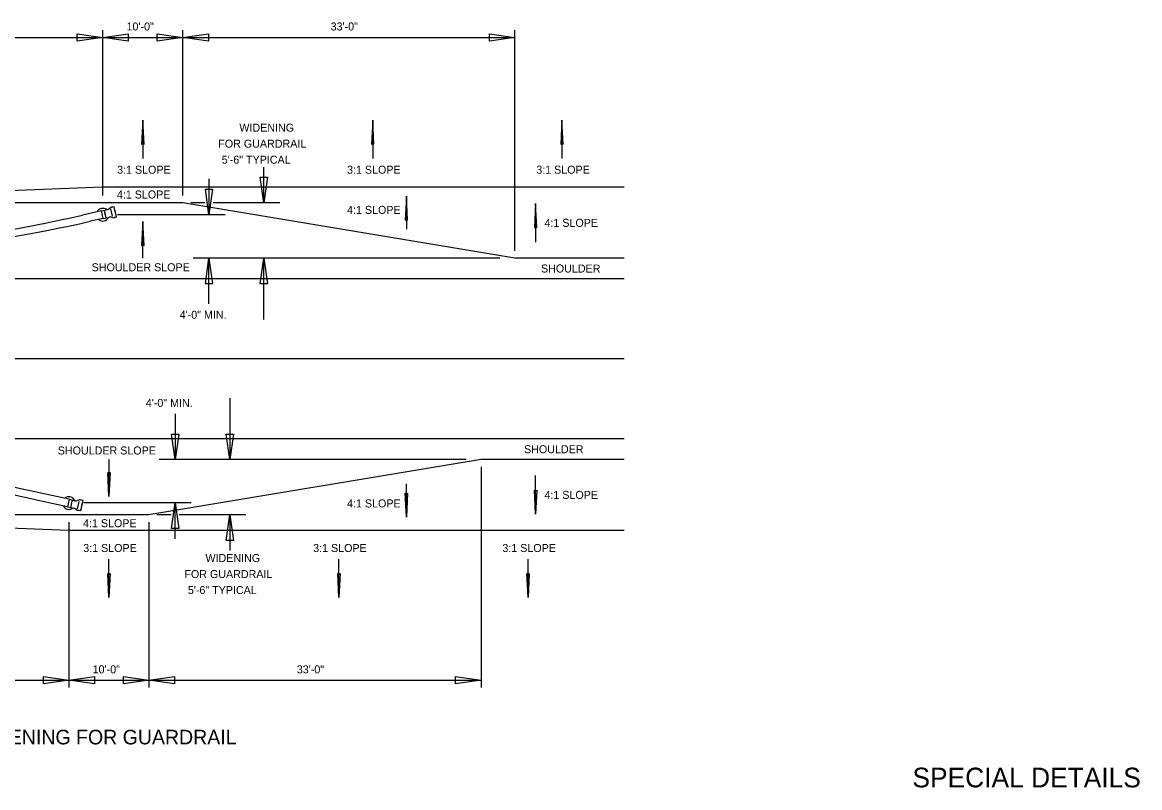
# Model space of a CAD drawing. Extents: x -149 to 1228740, y -106 to 152440.
# Drawn here: x -81.8 to -5.2, y -106 to -53.6 of the extents above; entities that cross this region are included whole.
import ezdxf

# ---------------------------------------------------------------- set-up
doc = ezdxf.new("R2010")
doc.units = 0
for name, color, linetype in [('R_Annotation', 7, 'Continuous'), ('R_Centerline', 7, 'Continuous'), ('R_Dimension', 7, 'Continuous'), ('R_Proposed Road', 7, 'Continuous'), ('R_Proposed Road_Lane', 7, 'Continuous'), ('R_Proposed Road_Shoulder', 7, 'Continuous'), ('R_Striping', 7, 'Continuous'), ('R_Water', 7, 'Continuous')]:
    doc.layers.add(name, color=color, linetype=linetype)

msp = doc.modelspace()

# ---------------------------------------------------------------- linework, layer by layer
at = {"layer": 'R_Annotation'}
for p, q in [((-73.52, -60.296), (-73.52, -62.938)), ((-57.763, -60.296), (-57.763, -62.938)), ((-44.799, -60.296), (-44.799, -62.938)), ((-55.458, -65.503), (-55.458, -67.782)), ((-46.61, -66.015), (-46.61, -68.657)), ((-73.52, -69.758), (-73.52, -67.236)), ((-75.84, -83.56), (-75.84, -86.082)), ((-46.61, -87.303), (-46.61, -84.661)), ((-55.458, -87.514), (-55.458, -85.235)), ((-75.84, -93.022), (-75.84, -90.38)), ((-60.084, -93.022), (-60.084, -90.38)), ((-47.12, -93.022), (-47.12, -90.38))]:
    msp.add_line(p, q, dxfattribs=at)
for points in [[(-73.52, -60.296), (-73.602, -61.941), (-73.52, -61.896), (-73.437, -61.941)], [(-57.763, -60.296), (-57.846, -61.941), (-57.763, -61.896), (-57.681, -61.941)], [(-44.799, -60.296), (-44.882, -61.941), (-44.799, -61.896), (-44.717, -61.941)], [(-55.458, -65.503), (-55.54, -67.148), (-55.458, -67.102), (-55.375, -67.148)], [(-46.61, -66.015), (-46.692, -67.661), (-46.61, -67.615), (-46.527, -67.661)], [(-73.52, -67.236), (-73.602, -68.882), (-73.52, -68.836), (-73.437, -68.882)], [(-75.84, -86.082), (-75.923, -84.437), (-75.84, -84.482), (-75.758, -84.437)], [(-46.61, -87.303), (-46.692, -85.658), (-46.61, -85.703), (-46.527, -85.658)], [(-55.458, -87.514), (-55.54, -85.869), (-55.458, -85.915), (-55.375, -85.869)], [(-75.84, -93.022), (-75.923, -91.377), (-75.84, -91.422), (-75.758, -91.377)], [(-60.084, -93.022), (-60.166, -91.377), (-60.084, -91.422), (-60.002, -91.377)], [(-47.12, -93.022), (-47.202, -91.377), (-47.12, -91.422), (-47.038, -91.377)]]:
    msp.add_lwpolyline(points, close=True, dxfattribs=at)
at = {"layer": 'R_Centerline'}
msp.add_line((-40.54, -76.659), (-122.83, -76.659), dxfattribs=at)
at = {"layer": 'R_Dimension'}
for p, q in [((-76.262, -65.465), (-76.262, -54.129)), ((-70.778, -65.465), (-70.778, -54.129)), ((-48.02, -69.258), (-48.02, -54.129)), ((-103.681, -54.629), (-76.262, -54.629)), ((-76.262, -54.629), (-70.778, -54.629)), ((-70.778, -54.629), (-48.02, -54.629)), ((-65.236, -65.965), (-65.236, -63.528)), ((-68.985, -64.322), (-68.985, -66.788)), ((-69.259, -65.965), (-70.229, -65.965)), ((-64.139, -65.965), (-68.71, -65.965)), ((-67.888, -66.788), (-75.249, -66.788)), ((-65.236, -73.96), (-65.236, -69.758)), ((-67.557, -79.358), (-67.557, -83.56)), ((-50.339, -84.06), (-50.339, -99.189)), ((-70.209, -86.53), (-77.57, -86.53)), ((-71.305, -88.997), (-71.305, -86.53)), ((-78.582, -87.853), (-78.582, -99.189)), ((-73.098, -87.853), (-73.098, -99.189)), ((-71.58, -87.353), (-72.55, -87.353)), ((-66.46, -87.353), (-71.031, -87.353)), ((-67.557, -87.353), (-67.557, -89.79)), ((-106.002, -98.689), (-78.582, -98.689)), ((-78.582, -98.689), (-73.098, -98.689)), ((-73.098, -98.689), (-50.339, -98.689))]:
    msp.add_line(p, q, dxfattribs=at)
for points in [[(-78.012, -54.379), (-76.262, -54.629), (-78.012, -54.879)], [(-74.512, -54.879), (-76.262, -54.629), (-74.512, -54.379)], [(-72.528, -54.379), (-70.778, -54.629), (-72.528, -54.879)], [(-69.028, -54.879), (-70.778, -54.629), (-69.028, -54.379)], [(-49.77, -54.379), (-48.02, -54.629), (-49.77, -54.879)], [(-64.986, -64.215), (-65.236, -65.965), (-65.486, -64.215)], [(-68.735, -65.038), (-68.985, -66.788), (-69.235, -65.038)], [(-69.235, -71.508), (-68.985, -69.758), (-68.735, -71.508)], [(-65.486, -71.508), (-65.236, -69.758), (-64.986, -71.508)], [(-71.055, -81.81), (-71.305, -83.56), (-71.555, -81.81)], [(-67.307, -81.81), (-67.557, -83.56), (-67.807, -81.81)], [(-71.555, -88.28), (-71.305, -86.53), (-71.055, -88.28)], [(-67.807, -89.103), (-67.557, -87.353), (-67.307, -89.103)], [(-80.332, -98.439), (-78.582, -98.689), (-80.332, -98.939)], [(-76.832, -98.939), (-78.582, -98.689), (-76.832, -98.439)], [(-74.848, -98.439), (-73.098, -98.689), (-74.848, -98.939)], [(-71.348, -98.939), (-73.098, -98.689), (-71.348, -98.439)], [(-52.089, -98.439), (-50.339, -98.689), (-52.089, -98.939)]]:
    msp.add_lwpolyline(points, close=True, dxfattribs=at)
for points in [[(-49.054, -69.758), (-70.081, -69.758)], [(-68.985, -72.881), (-68.985, -69.758)], [(-71.305, -80.437), (-71.305, -83.56)], [(-51.373, -83.56), (-61.923, -83.56), (-65.038, -83.56), (-72.402, -83.56)]]:
    msp.add_lwpolyline(points, dxfattribs=at)
at = {"layer": 'R_Proposed Road'}
for p, q in [((-76.359, -66.514), (-77.642, -66.803)), ((-76.359, -66.514), (-75.923, -66.416)), ((-76.242, -67.035), (-76.359, -66.514)), ((-76.035, -66.988), (-76.152, -66.468)), ((-76.122, -66.601), (-76.15, -66.475)), ((-75.744, -66.317), (-75.845, -66.39)), ((-75.589, -66.888), (-75.704, -66.375)), ((-75.479, -66.234), (-75.675, -66.278)), ((-75.608, -66.263), (-75.643, -66.271)), ((-75.459, -66.325), (-75.479, -66.234)), ((-75.318, -66.95), (-75.479, -66.234)), ((-75.428, -66.46), (-75.45, -66.361)), ((-75.401, -66.58), (-75.419, -66.501)), ((-76.242, -67.035), (-77.119, -67.232)), ((-76.242, -67.035), (-75.806, -66.937)), ((-76.075, -66.811), (-76.113, -66.642)), ((-75.592, -66.98), (-75.692, -66.947)), ((-75.418, -66.973), (-75.482, -66.987)), ((-75.318, -66.95), (-75.457, -66.981)), ((-75.372, -66.71), (-75.39, -66.628)), ((-75.342, -66.844), (-75.361, -66.758)), ((-78.563, -86.283), (-79.439, -86.086)), ((-78.563, -86.283), (-78.68, -86.804)), ((-78.563, -86.283), (-78.127, -86.381)), ((-78.356, -86.33), (-78.473, -86.851)), ((-78.395, -86.507), (-78.433, -86.676)), ((-77.909, -86.43), (-78.025, -86.944)), ((-77.913, -86.338), (-78.012, -86.372)), ((-77.739, -86.346), (-77.802, -86.331)), ((-77.639, -86.368), (-77.8, -87.084)), ((-77.639, -86.368), (-77.778, -86.337)), ((-77.663, -86.475), (-77.682, -86.56)), ((-78.68, -86.804), (-79.962, -86.515)), ((-78.68, -86.804), (-78.244, -86.902)), ((-78.443, -86.717), (-78.471, -86.843)), ((-78.065, -87.001), (-78.166, -86.928)), ((-78.065, -87.001), (-78.166, -86.928)), ((-77.8, -87.084), (-77.995, -87.04)), ((-77.8, -87.084), (-77.995, -87.04)), ((-77.929, -87.055), (-77.963, -87.047)), ((-77.929, -87.055), (-77.963, -87.047)), ((-77.779, -86.993), (-77.8, -87.084)), ((-77.779, -86.993), (-77.8, -87.084)), ((-77.749, -86.858), (-77.771, -86.957)), ((-77.722, -86.739), (-77.74, -86.817)), ((-77.693, -86.608), (-77.711, -86.69))]:
    msp.add_line(p, q, dxfattribs=at)
for points in [[(-40.54, -64.89), (-76.262, -64.89), (-103.681, -65.965)], [(-40.54, -88.428), (-78.582, -88.428), (-106.002, -87.353)]]:
    msp.add_lwpolyline(points, dxfattribs=at)
for centre, radius, start, end in [((-76.262, -66.778), 0.435, 52.30361, 152.92389), ((-75.956, -66.191), 0.227, 278.33469, 299.17257), ((-75.956, -66.191), 0.227, 278.33469, 299.17257), ((-75.617, -66.462), 0.193, 107.55156, 131.26204), ((-75.617, -66.462), 0.193, 97.80442, 101.4922), ((-104.241, 51.438), 121.196, 270, 282.67799), ((-101.19, 39.773), 109.68, 270, 282.67799), ((-76.262, -66.778), 0.435, 228.5928, 336.76317), ((-75.76, -67.062), 0.134, 59.28209, 109.60131), ((-75.522, -66.749), 0.241, 253.05396, 285.70011), ((-75.522, -66.749), 0.241, 279.46684, 279.65599), ((-103.511, -193.091), 109.68, 77.32201, 90), ((-106.562, -204.756), 121.196, 77.32201, 90), ((-78.583, -86.54), 0.435, 23.23683, 131.4072), ((-78.081, -86.256), 0.134, 250.39869, 300.71791), ((-77.843, -86.569), 0.241, 74.29989, 106.94604), ((-77.843, -86.569), 0.241, 80.34401, 80.53316), ((-78.583, -86.54), 0.435, 207.07611, 307.69639), ((-78.277, -87.127), 0.227, 60.82743, 81.66531), ((-78.277, -87.127), 0.227, 60.82743, 81.66531), ((-77.937, -86.856), 0.193, 228.73796, 252.44844), ((-77.937, -86.856), 0.193, 228.73796, 252.44844), ((-77.937, -86.856), 0.193, 258.5078, 262.19558), ((-77.937, -86.856), 0.193, 258.5078, 262.19558)]:
    msp.add_arc(centre, radius, start, end, dxfattribs=at)
at = {"layer": 'R_Proposed Road_Lane'}
for points in [[(-40.54, -71.175), (-50.279, -71.175), (-51.306, -71.175), (-59.602, -71.175), (-62.717, -71.175), (-90.137, -71.175), (-96.257, -71.175), (-96.893, -71.175), (-119.858, -71.175)], [(-40.54, -82.143), (-46.457, -82.143), (-47.484, -82.143), (-55.78, -82.143), (-58.895, -82.143), (-86.314, -82.143), (-92.435, -82.143), (-93.071, -82.143), (-122.739, -82.143)]]:
    msp.add_lwpolyline(points, dxfattribs=at)
at = {"layer": 'R_Proposed Road_Shoulder'}
for points in [[(-48.02, -69.758), (-70.778, -65.965), (-113.633, -65.965), (-113.633, -69.21)], [(-40.54, -69.758), (-48.02, -69.758)], [(-50.339, -83.56), (-73.098, -87.353), (-115.953, -87.353), (-115.953, -84.108)], [(-40.54, -83.56), (-50.339, -83.56)]]:
    msp.add_lwpolyline(points, dxfattribs=at)
at = {"layer": 'R_Water'}
for p, q in [((-71.58, -87.353), (-72.55, -87.353)), ((-66.46, -87.353), (-71.031, -87.353))]:
    msp.add_line(p, q, dxfattribs=at)

# ---------------------------------------------------------------- texts
at = {"layer": 'R_Annotation'}
for s, height, p in [('10\'-0"', 0.55, (-74.639, -54.154)), ('33\'-0"', 0.55, (-60.653, -54.154)), ('WIDENING', 0.5484, (-66.905, -61.089)), ('FOR GUARDRAIL', 0.5484, (-68.349, -62.186)), ('5\'-6" TYPICAL', 0.5484, (-68.112, -63.282)), ('3:1 SLOPE', 0.5484, (-75.281, -63.97)), ('3:1 SLOPE', 0.5484, (-59.525, -63.97)), ('3:1 SLOPE', 0.5484, (-46.561, -63.97)), ('4:1 SLOPE', 0.5484, (-75.295, -65.669)), ('4:1 SLOPE', 0.5484, (-59.525, -66.724)), ('4:1 SLOPE', 0.5484, (-45.999, -67.611)), ('SHOULDER SLOPE', 0.5484, (-77.026, -70.655)), ('SHOULDER', 0.5484, (-46.238, -70.741)), ('4\'-0" MIN.', 0.5484, (-70.993, -73.911)), ('4\'-0" MIN.', 0.5484, (-73.313, -79.956)), ('SHOULDER SLOPE', 0.5484, (-79.347, -83.212)), ('SHOULDER', 0.5484, (-47.398, -83.126)), ('4:1 SLOPE', 0.5484, (-45.999, -86.256)), ('4:1 SLOPE', 0.5484, (-59.525, -86.841)), ('4:1 SLOPE', 0.5484, (-77.616, -88.198)), ('3:1 SLOPE', 0.5484, (-77.602, -89.897)), ('3:1 SLOPE', 0.5484, (-61.846, -89.897)), ('3:1 SLOPE', 0.5484, (-48.882, -89.897)), ('WIDENING', 0.5484, (-69.226, -90.584)), ('FOR GUARDRAIL', 0.5484, (-70.67, -91.681)), ('5\'-6" TYPICAL', 0.5484, (-70.433, -92.778)), ('10\'-0"', 0.55, (-76.96, -98.214)), ('33\'-0"', 0.55, (-62.972, -98.214)), ('DETAILS OF ROADWAY WIDENING FOR GUARDRAIL', 1, (-100.754, -103.081))]:
    msp.add_text(s, height=height, dxfattribs=at).set_placement(p)
at = {"layer": 'R_Striping'}
msp.add_text('SPECIAL DETAILS', height=1.35, dxfattribs=at).set_placement((-20.787, -106.028))

doc.saveas('drawing.dxf')
